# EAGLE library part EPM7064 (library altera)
EPM7064 MAX 7000 family
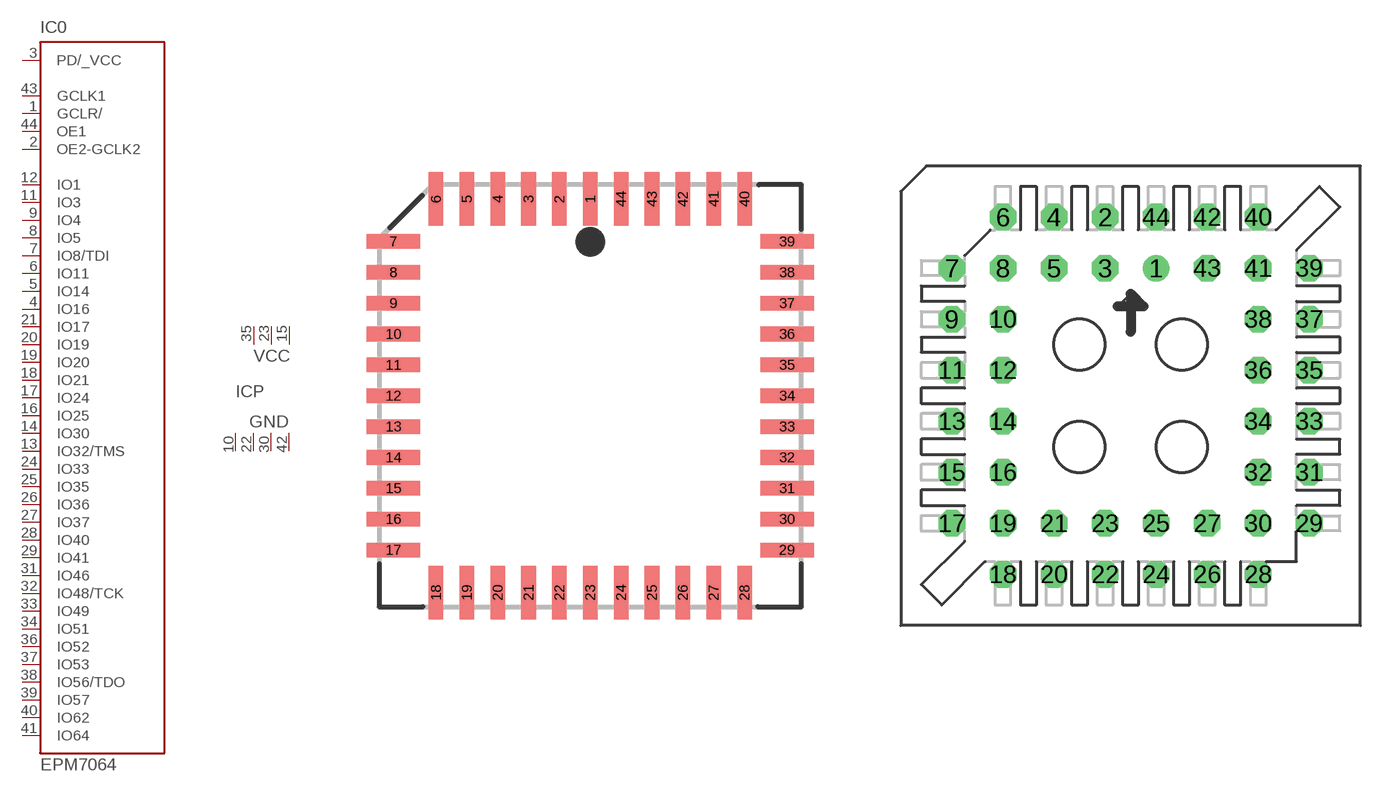
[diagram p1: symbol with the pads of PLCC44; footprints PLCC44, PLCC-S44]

Designator prefix IC; gates 0=7064-44 P=PWR3-4

## EPM7064J44 (OC_FARNELL: unknown; OC_NEWARK: unknown)  [PLCC44]
1  0:GCLR/  in
2  0:OE2-GCLK2  in
3  0:PD/_VCC  pas
4  0:IO16
5  0:IO14
6  0:IO11
7  0:IO8/TDI
8  0:IO5
9  0:IO4
10  P:GND  pwr
11  0:IO3
12  0:IO1
13  0:IO32/TMS
14  0:IO30
15  P:VCC  pwr
16  0:IO25
17  0:IO24
18  0:IO21
19  0:IO20
20  0:IO19
21  0:IO17
22  P:GND  pwr
23  P:VCC  pwr
24  0:IO33
25  0:IO35
26  0:IO36
27  0:IO37
28  0:IO40
29  0:IO41
30  P:GND  pwr
31  0:IO46
32  0:IO48/TCK
33  0:IO49
34  0:IO51
35  P:VCC  pwr
36  0:IO52
37  0:IO53
38  0:IO56/TDO
39  0:IO57
40  0:IO62
41  0:IO64
42  P:GND  pwr
43  0:GCLK1  in
44  0:OE1  in

## EPM7064S44 (MPN: EPM7064SLC44-10N; OC_FARNELL: 1549449; OC_NEWARK: 51R0526)  [PLCC-S44]
Pads as for PLCC44

## EPM7064T44 (MPN: EPM7064TC44-15; OC_FARNELL: unknown; OC_NEWARK: 51R9653)  [TQFP44]
1  0:IO8/TDI
2  0:IO5
3  0:IO4
4  P:GND  pwr
5  0:IO3
6  0:IO1
7  0:IO32/TMS
8  0:IO30
9  0:PD/_VCC  pas
10  0:IO25
11  0:IO24
12  0:IO21
13  0:IO20
14  0:IO19
15  0:IO17
16  P:GND  pwr
17  P:VCC  pwr
18  0:IO33
19  0:IO35
20  0:IO36
21  0:IO37
22  0:IO40
23  0:IO41
24  P:GND  pwr
25  0:IO46
26  0:IO48/TCK
27  0:IO49
28  0:IO51
29  P:VCC  pwr
30  0:IO52
31  0:IO53
32  0:IO56/TDO
33  0:IO57
34  0:IO62
35  0:IO64
36  P:GND  pwr
37  0:GCLK1  in
38  0:OE1  in
39  0:GCLR/  in
40  0:OE2-GCLK2  in
41  P:VCC  pwr
42  0:IO16
43  0:IO14
44  0:IO11

## Footprint PLCC44 (pad centres in mm)
Plastic J-Lead Chip Carrier
smd 0.6 x 2.2: 1 0,8.1; 2 -1.27,8.1; 3 -2.54,8.1; 4 -3.81,8.1; 5 -5.08,8.1; 6 -6.35,8.1; 18 -6.35,-8.1; 19 -5.08,-8.1; 20 -3.81,-8.1; 21 -2.54,-8.1; 22 -1.27,-8.1; 23 0,-8.1; 24 1.27,-8.1; 25 2.54,-8.1; 26 3.81,-8.1; 27 5.08,-8.1; 28 6.35,-8.1; 40 6.35,8.1; 41 5.08,8.1; 42 3.81,8.1; 43 2.54,8.1; 44 1.27,8.1
smd 2.2 x 0.6: 7 -8.1,6.35; 8 -8.1,5.08; 9 -8.1,3.81; 10 -8.1,2.54; 11 -8.1,1.27; 12 -8.1,0; 13 -8.1,-1.27; 14 -8.1,-2.54; 15 -8.1,-3.81; 16 -8.1,-5.08; 17 -8.1,-6.35; 29 8.1,-6.35; 30 8.1,-5.08; 31 8.1,-3.81; 32 8.1,-2.54; 33 8.1,-1.27; 34 8.1,0; 35 8.1,1.27; 36 8.1,2.54; 37 8.1,3.81; 38 8.1,5.08; 39 8.1,6.35

## Footprint PLCC-S44 (pad centres in mm)
Plastic Leaded Chip Carrier Socked
drill 0.813 round: 1 1.27,6.35
drill 0.813 octagon: 2 -1.27,8.89; 3 -1.27,6.35; 4 -3.81,8.89; 5 -3.81,6.35; 6 -6.35,8.89; 7 -8.89,6.35; 8 -6.35,6.35; 9 -8.89,3.81; 10 -6.35,3.81; 11 -8.89,1.27; 12 -6.35,1.27; 13 -8.89,-1.27; 14 -6.35,-1.27; 15 -8.89,-3.81; 16 -6.35,-3.81; 17 -8.89,-6.35; 18 -6.35,-8.89; 19 -6.35,-6.35; 20 -3.81,-8.89; 21 -3.81,-6.35; 22 -1.27,-8.89; 23 -1.27,-6.35; 24 1.27,-8.89; 25 1.27,-6.35; 26 3.81,-8.89; 27 3.81,-6.35; 28 6.35,-8.89; 29 8.89,-6.35; 30 6.35,-6.35; 31 8.89,-3.81; 32 6.35,-3.81; 33 8.89,-1.27; 34 6.35,-1.27; 35 8.89,1.27; 36 6.35,1.27; 37 8.89,3.81; 38 6.35,3.81; 39 8.89,6.35; 40 6.35,8.89; 41 6.35,6.35; 42 3.81,8.89; 43 3.81,6.35; 44 1.27,8.89

## Footprint TQFP44 (pad centres in mm)
Plastic Thin Quad Flat Pack
smd 1.5 x 0.5: 1 -5.8,4; 2 -5.8,3.2; 3 -5.8,2.4; 4 -5.8,1.6; 5 -5.8,0.8; 6 -5.8,0; 7 -5.8,-0.8; 8 -5.8,-1.6; 9 -5.8,-2.4; 10 -5.8,-3.2; 11 -5.8,-4; 23 5.8,-4; 24 5.8,-3.2; 25 5.8,-2.4; 26 5.8,-1.6; 27 5.8,-0.8; 28 5.8,0; 29 5.8,0.8; 30 5.8,1.6; 31 5.8,2.4; 32 5.8,3.2; 33 5.8,4
smd 0.5 x 1.5: 12 -4,-5.8; 13 -3.2,-5.8; 14 -2.4,-5.8; 15 -1.6,-5.8; 16 -0.8,-5.8; 17 0,-5.8; 18 0.8,-5.8; 19 1.6,-5.8; 20 2.4,-5.8; 21 3.2,-5.8; 22 4,-5.8; 34 4,5.8; 35 3.2,5.8; 36 2.4,5.8; 37 1.6,5.8; 38 0.8,5.8; 39 0,5.8; 40 -0.8,5.8; 41 -1.6,5.8; 42 -2.4,5.8; 43 -3.2,5.8; 44 -4,5.8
